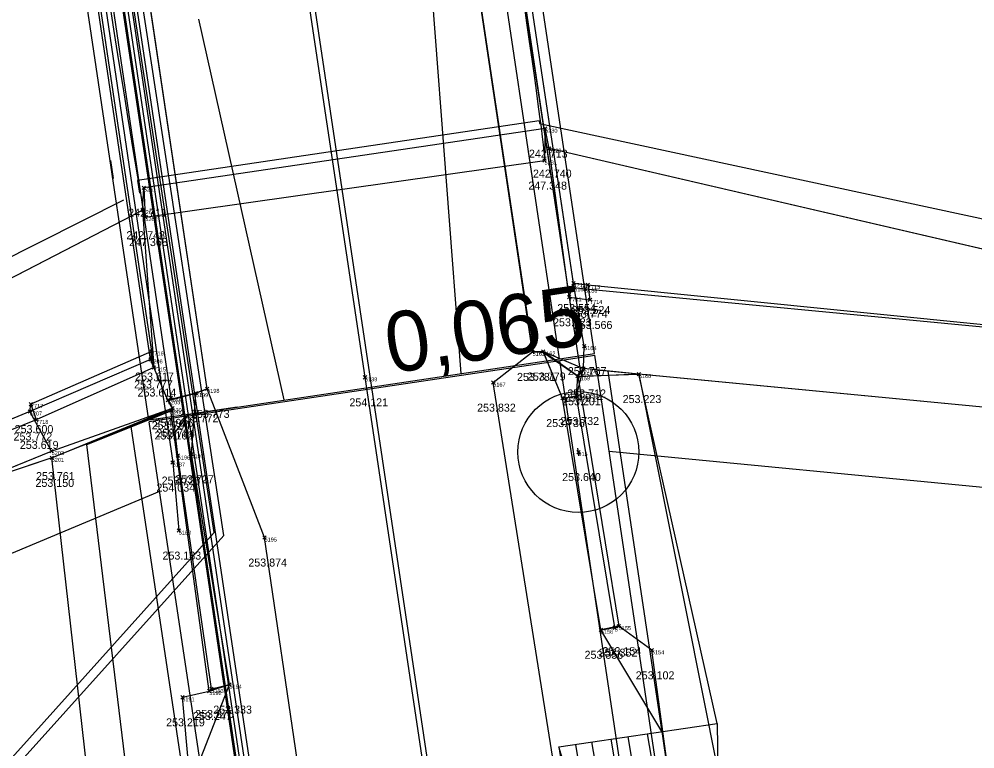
# Model space of a CAD drawing. Extents: x -809973 to -809318, y -1011363 to -1010505.
# Drawn here: x -809864.63 to -809852.68, y -1010880.51 to -1010871.39 of the extents above; entities that cross this region are included whole.
import ezdxf

# ---------------------------------------------------------------- set-up
doc = ezdxf.new("R2010")
doc.units = 0
for name, color, linetype in [('18b - zaměření - čísla bodů', 7, 'Continuous'), ('18c - zaměření - výšky', 7, 'Continuous'), ('Návrh', 7, 'Continuous'), ('SO03 - Železniční svršek', 7, 'Continuous'), ('SO04 - Železniční spodek', 7, 'Continuous'), ('SO05 - Úprava kabelů', 7, 'Continuous'), ('SO_02', 7, 'Continuous'), ('stav_stav', 7, 'Continuous'), ('žel svršek_hrany', 7, 'Continuous')]:
    doc.layers.add(name, color=color, linetype=linetype)

# ---------------------------------------------------------------- blocks, each defined once
blk = doc.blocks.new('POINT_DISPLAY')
for p, q in [((-0.021, -0.021), (0.021, 0.021)), ((-0.021, 0.021), (0.021, -0.021))]:
    blk.add_line(p, q)
blk = doc.blocks.new('rampa')
at = {"layer": 'žel svršek_hrany'}
for p, q in [((-790325.466, -1020009.334), (-790322.95, -1020002.801)), ((-790327.333, -1020008.615), (-790324.882, -1020004.201)), ((-790326.679, -1020008.867), (-790324.882, -1020004.201)), ((-790324.322, -1020004.416), (-790325.466, -1020009.334)), ((-790326.278, -1020009.021), (-790325.731, -1020007.52)), ((-790325.85, -1020009.186), (-790325.303, -1020007.685)), ((-790326.506, -1020008.933), (-790326.284, -1020008.32)), ((-790326.078, -1020009.098), (-790325.856, -1020008.484)), ((-790325.466, -1020009.334), (-790327.333, -1020008.615)), ((-790325.466, -1020009.334), (-790327.333, -1020008.615)), ((-790325.66, -1020009.259), (-790325.438, -1020008.645))]:
    blk.add_line(p, q, dxfattribs=at)

msp = doc.modelspace()

# ---------------------------------------------------------------- linework, layer by layer
at = {"layer": 'Návrh'}
msp.add_line((-809857.286, -1010895.613), (-809869.822, -1010811.804), dxfattribs=at)
at = {"layer": 'SO03 - Železniční svršek'}
for p, q in [((-809858.071, -1010875.559), (-809858.211, -1010875.546)), ((-809858.086, -1010875.549), (-809858.211, -1010875.554)), ((-809857.638, -1010875.859), (-809858.086, -1010875.549)), ((-809857.838, -1010876.123), (-809858.071, -1010875.559)), ((-809856.883, -1010875.823), (-809857.638, -1010875.859)), ((-809855.903, -1010880.191), (-809856.883, -1010875.823)), ((-809862.763, -1010876.152), (-809862.419, -1010876.062)), ((-809862.708, -1010876.25), (-809862.763, -1010876.152)), ((-809857.359, -1010879.02), (-809857.838, -1010876.123)), ((-809863.782, -1010876.706), (-809862.73, -1010876.281)), ((-809862.73, -1010876.281), (-809862.708, -1010876.25)), ((-809863.235, -1010881.193), (-809863.782, -1010876.706)), ((-809856.596, -1010880.293), (-809857.359, -1010879.02)), ((-809862.543, -1010881.091), (-809862, -1010879.706))]:
    msp.add_line(p, q, dxfattribs=at)
for points in [[(-809862, -1010879.706), (-809862.476, -1010876.825), (-809862.419, -1010876.062), (-809862.279, -1010876.008), (-809867.764, -1010839.12), (-809868.277, -1010839.183), (-809869.024, -1010838.237), (-809869.537, -1010834.33)], [(-809863.296, -1010838.436), (-809863.759, -1010838.589), (-809858.21, -1010875.554)]]:
    msp.add_lwpolyline(points, dxfattribs=at)
at = {"layer": 'SO04 - Železniční spodek'}
for points in [[(-809857.269, -1010875.786), (-809854.226, -1010896.132), (-809854.078, -1010897.121)], [(-809863.233, -1010876.477), (-809860.16, -1010897.02)]]:
    msp.add_lwpolyline(points, dxfattribs=at)
at = {"layer": 'SO05 - Úprava kabelů'}
for points in [[(-809832.494, -1011018.409), (-809834.046, -1011017.811), (-809840.102, -1011020.003), (-809840.886, -1011019.699), (-809849.784, -1011002.747), (-809854.105, -1010999.74), (-809859.871, -1010979.608), (-809861.054, -1010971.463), (-809873.181, -1010917.053), (-809875.79, -1010892.925), (-809862.192, -1010877.803), (-809870.3, -1010824.924)], [(-809832.452, -1011018.3), (-809834.045, -1011017.686), (-809840.101, -1011019.878), (-809840.803, -1011019.606), (-809849.694, -1011002.668), (-809854.004, -1010999.668), (-809859.756, -1010979.584), (-809860.94, -1010971.442), (-809873.066, -1010917.034), (-809875.669, -1010892.964), (-809862.069, -1010877.84), (-809862.069, -1010877.84), (-809870.184, -1010824.906)], [(-809832.452, -1011018.3), (-809834.599, -1011012.541), (-809836.558, -1011007.657), (-809839.63, -1011000.177), (-809840.754, -1010995.474), (-809845.885, -1010976.431), (-809847.466, -1010970.457), (-809849.998, -1010958.97), (-809853.746, -1010939.574), (-809862.448, -1010886.367), (-809861.681, -1010881.903), (-809870.184, -1010824.906)], [(-809832.343, -1011018.259), (-809834.49, -1011012.499), (-809836.45, -1011007.613), (-809839.519, -1011000.141), (-809840.641, -1010995.445), (-809845.773, -1010976.401), (-809847.353, -1010970.429), (-809849.884, -1010958.947), (-809853.631, -1010939.554), (-809862.33, -1010886.367), (-809861.563, -1010881.905), (-809870.069, -1010824.889)]]:
    msp.add_lwpolyline(points, dxfattribs=at)
at = {"layer": 'SO_02'}
for p, q in [((-809861.747, -1010881.746), (-809868.926, -1010833.75)), ((-809861.648, -1010881.731), (-809868.827, -1010833.736)), ((-809857.874, -1010875.633), (-809863.458, -1010838.296)), ((-809857.438, -1010875.568), (-809863.023, -1010838.231)), ((-809857.7, -1010874.685), (-809863.148, -1010838.433)), ((-809863.285, -1010838.455), (-809857.753, -1010874.863)), ((-809862.571, -1010876.336), (-809868.156, -1010838.999)), ((-809863.006, -1010876.401), (-809868.591, -1010839.064)), ((-809868.363, -1010839.157), (-809862.976, -1010875.541)), ((-809859.477, -1010870.952), (-809859.109, -1010875.818)), ((-809862.387, -1010871.385), (-809861.319, -1010876.147)), ((-809858.129, -1010872.656), (-809863.148, -1010873.404)), ((-809858.129, -1010872.656), (-809858.124, -1010872.691)), ((-809858.124, -1010872.691), (-809844.481, -1010875.628)), ((-809858.054, -1010872.755), (-809863.071, -1010873.493)), ((-809863.489, -1010873.152), (-809863.455, -1010873.378)), ((-809863.052, -1010873.86), (-809858.062, -1010873.154)), ((-809863.148, -1010873.404), (-809863.125, -1010873.561)), ((-809876.864, -1010880.47), (-809863.32, -1010873.645)), ((-809863.086, -1010873.774), (-809862.946, -1010875.741)), ((-809857.555, -1010874.757), (-809844.518, -1010876.01)), ((-809857.52, -1010874.709), (-809844.518, -1010876.01)), ((-809857.753, -1010874.863), (-809857.494, -1010874.896)), ((-809862.976, -1010875.541), (-809862.989, -1010875.64)), ((-809857.874, -1010875.633), (-809857.438, -1010875.568)), ((-809857.871, -1010875.653), (-809857.435, -1010875.588)), ((-809856.685, -1010880.607), (-809857.435, -1010875.588)), ((-809862.571, -1010876.336), (-809857.874, -1010875.633)), ((-809862.568, -1010876.355), (-809857.871, -1010875.653)), ((-809857.12, -1010880.672), (-809857.871, -1010875.653)), ((-809862.946, -1010875.741), (-809864.417, -1010876.396)), ((-809844.618, -1010877), (-809857.408, -1010875.773)), ((-809844.618, -1010877), (-809856.883, -1010875.823)), ((-809864.497, -1010876.291), (-809864.482, -1010876.198)), ((-809864.223, -1010876.786), (-809864.497, -1010876.291)), ((-809861.904, -1010876.236), (-809862.571, -1010876.336)), ((-809864.417, -1010876.396), (-809876.573, -1010881.314)), ((-809862.571, -1010876.336), (-809863.006, -1010876.401)), ((-809862.568, -1010876.355), (-809863.004, -1010876.421)), ((-809862.253, -1010881.44), (-809863.004, -1010876.421)), ((-809862.677, -1010876.555), (-809862.506, -1010876.324)), ((-809861.818, -1010881.375), (-809862.568, -1010876.355)), ((-809844.714, -1010877.995), (-809857.255, -1010876.792))]:
    msp.add_line(p, q, dxfattribs=at)
for points in [[(-809844.518, -1010876.01), (-809846.267, -1010875.73), (-809858.004, -1010873.004), (-809858.054, -1010872.755), (-809858.062, -1010873.154)], [(-809857.753, -1010874.863), (-809858.004, -1010873.004)], [(-809880.813, -1010883.644), (-809881.049, -1010884.006), (-809881.035, -1010883.822), (-809875.603, -1010880.245), (-809863.086, -1010873.774), (-809863.071, -1010873.493), (-809863.052, -1010873.86)], [(-809857.753, -1010874.863), (-809857.7, -1010874.685), (-809857.52, -1010874.709), (-809857.494, -1010874.896)], [(-809857.691, -1010874.74), (-809857.7, -1010874.685)], [(-809857.691, -1010874.74), (-809857.555, -1010874.757)], [(-809862.946, -1010875.741), (-809862.976, -1010875.541), (-809864.482, -1010876.198), (-809864.417, -1010876.396)], [(-809862.989, -1010875.64), (-809864.497, -1010876.291)], [(-809862.712, -1010876.25), (-809862.734, -1010876.278), (-809864.222, -1010876.871), (-809865.405, -1010877.268), (-809864.223, -1010876.786), (-809862.712, -1010876.25), (-809862.769, -1010876.151)], [(-809864.497, -1010876.291), (-809876.573, -1010881.314), (-809880.813, -1010883.644)], [(-809862.873, -1010877.291), (-809875.888, -1010882.745), (-809880.049, -1010885.032)]]:
    msp.add_lwpolyline(points, dxfattribs=at)
for centre, major_axis, ratio, start_param, end_param in [((-809858.765, -1010868.548), (0.706, -4.61), 0.011125, 6.242864, 9.451152), ((-809863.75, -1010869.267), (0.697, -4.596), 0.009302, 3.125155, 6.319851)]:
    msp.add_ellipse(centre, major_axis=major_axis, ratio=ratio, start_param=start_param, end_param=end_param, dxfattribs=at)
at = {"layer": 'stav_stav'}
for p, q in [((-809857.7, -1010874.685), (-809863.148, -1010838.433)), ((-809863.285, -1010838.455), (-809857.753, -1010874.863)), ((-809863.205, -1010838.533), (-809857.614, -1010875.806)), ((-809857.691, -1010874.74), (-809863.152, -1010838.466)), ((-809858.211, -1010875.546), (-809863.759, -1010838.589)), ((-809863.759, -1010838.589), (-809858.211, -1010875.546)), ((-809868.363, -1010839.157), (-809862.976, -1010875.541)), ((-809868.218, -1010839.075), (-809862.732, -1010876.12)), ((-809862.279, -1010876.008), (-809867.764, -1010839.12)), ((-809862.279, -1010876.008), (-809867.764, -1010839.12)), ((-809862.989, -1010875.64), (-809868.39, -1010839.215)), ((-809868.273, -1010839.19), (-809862.71, -1010876.93)), ((-809860.306, -1010875.864), (-809863.238, -1010856.222)), ((-809858.054, -1010872.755), (-809863.071, -1010873.493)), ((-809858.054, -1010872.755), (-809858.062, -1010873.154)), ((-809858.004, -1010873.004), (-809858.054, -1010872.755)), ((-809857.753, -1010874.863), (-809858.004, -1010873.004)), ((-809846.267, -1010875.73), (-809858.004, -1010873.004)), ((-809863.086, -1010873.774), (-809863.071, -1010873.493)), ((-809863.071, -1010873.493), (-809863.052, -1010873.86)), ((-809875.603, -1010880.245), (-809863.086, -1010873.774)), ((-809863.086, -1010873.774), (-809862.946, -1010875.741)), ((-809857.753, -1010874.863), (-809857.7, -1010874.685)), ((-809857.691, -1010874.74), (-809857.7, -1010874.685)), ((-809857.7, -1010874.685), (-809857.52, -1010874.709)), ((-809857.691, -1010874.74), (-809857.555, -1010874.757)), ((-809857.568, -1010875.474), (-809857.691, -1010874.74)), ((-809857.555, -1010874.757), (-809844.518, -1010876.01)), ((-809857.52, -1010874.709), (-809844.518, -1010876.01)), ((-809857.52, -1010874.709), (-809857.494, -1010874.896)), ((-809857.753, -1010874.863), (-809857.494, -1010874.896)), ((-809857.575, -1010875.753), (-809857.568, -1010875.474)), ((-809862.976, -1010875.541), (-809864.482, -1010876.198)), ((-809862.976, -1010875.541), (-809862.989, -1010875.64)), ((-809862.946, -1010875.741), (-809862.976, -1010875.541)), ((-809858.703, -1010875.93), (-809858.211, -1010875.546)), ((-809858.079, -1010875.541), (-809858.211, -1010875.546)), ((-809858.211, -1010875.546), (-809858.079, -1010875.541)), ((-809857.838, -1010876.123), (-809858.079, -1010875.541)), ((-809858.079, -1010875.541), (-809857.575, -1010875.753)), ((-809857.648, -1010875.851), (-809858.079, -1010875.541)), ((-809857.838, -1010876.123), (-809858.079, -1010875.541)), ((-809858.079, -1010875.541), (-809857.648, -1010875.851)), ((-809858.079, -1010875.541), (-809857.575, -1010875.753)), ((-809862.989, -1010875.64), (-809864.497, -1010876.291)), ((-809862.769, -1010876.151), (-809862.989, -1010875.64)), ((-809862.946, -1010875.741), (-809864.417, -1010876.396)), ((-809857.662, -1010876.097), (-809857.575, -1010875.753)), ((-809857.648, -1010875.851), (-809857.575, -1010875.753)), ((-809857.575, -1010875.753), (-809857.648, -1010875.851)), ((-809857.648, -1010875.851), (-809856.883, -1010875.823)), ((-809856.883, -1010875.823), (-809857.575, -1010875.753)), ((-809844.618, -1010877), (-809856.883, -1010875.823)), ((-809856.883, -1010875.823), (-809855.422, -1010883.15)), ((-809844.618, -1010877), (-809856.883, -1010875.823)), ((-809858.786, -1010885.982), (-809860.306, -1010875.864)), ((-809857.441, -1010883.897), (-809858.703, -1010875.93)), ((-809857.662, -1010876.097), (-809857.648, -1010875.851)), ((-809857.648, -1010875.851), (-809857.134, -1010878.975)), ((-809862.419, -1010876.062), (-809862.769, -1010876.151)), ((-809862.419, -1010876.062), (-809862.769, -1010876.151)), ((-809862.476, -1010876.825), (-809862.419, -1010876.062)), ((-809862.476, -1010876.825), (-809862.419, -1010876.062)), ((-809862.279, -1010876.008), (-809862.419, -1010876.062)), ((-809862.419, -1010876.062), (-809862.279, -1010876.008)), ((-809861.561, -1010877.867), (-809862.279, -1010876.008)), ((-809864.497, -1010876.291), (-809864.482, -1010876.198)), ((-809864.482, -1010876.198), (-809864.417, -1010876.396)), ((-809862.712, -1010876.25), (-809862.769, -1010876.151)), ((-809862.769, -1010876.151), (-809862.712, -1010876.25)), ((-809857.838, -1010876.123), (-809857.662, -1010876.097)), ((-809857.359, -1010879.02), (-809857.838, -1010876.123)), ((-809857.359, -1010879.02), (-809857.838, -1010876.123)), ((-809857.183, -1010878.994), (-809857.662, -1010876.097)), ((-809864.497, -1010876.291), (-809876.573, -1010881.314)), ((-809864.223, -1010876.786), (-809864.497, -1010876.291)), ((-809864.223, -1010876.786), (-809862.712, -1010876.25)), ((-809864.222, -1010876.871), (-809862.712, -1010876.25)), ((-809862.734, -1010876.278), (-809864.222, -1010876.871)), ((-809862.734, -1010876.278), (-809864.222, -1010876.871)), ((-809862.712, -1010876.25), (-809862.734, -1010876.278)), ((-809862.712, -1010876.25), (-809862.734, -1010876.278)), ((-809862.252, -1010879.786), (-809862.734, -1010876.278)), ((-809862.645, -1010876.842), (-809862.712, -1010876.25)), ((-809864.417, -1010876.396), (-809876.573, -1010881.314)), ((-809865.405, -1010877.268), (-809864.223, -1010876.786)), ((-809857.632, -1010876.847), (-809857.646, -1010876.749)), ((-809864.222, -1010876.871), (-809865.405, -1010877.268)), ((-809864.222, -1010876.871), (-809865.405, -1010877.268)), ((-809863.59, -1010882.451), (-809864.222, -1010876.871)), ((-809862.226, -1010879.76), (-809862.645, -1010876.842)), ((-809862, -1010879.706), (-809862.476, -1010876.825)), ((-809862, -1010879.706), (-809862.476, -1010876.825)), ((-809862.71, -1010876.93), (-809862.634, -1010877.78)), ((-809857.871, -1010903.005), (-809861.561, -1010877.867)), ((-809857.134, -1010878.975), (-809857.359, -1010879.02)), ((-809857.134, -1010878.975), (-809857.359, -1010879.02)), ((-809857.359, -1010879.02), (-809857.183, -1010878.994)), ((-809857.183, -1010878.994), (-809857.134, -1010878.975)), ((-809856.72, -1010879.277), (-809857.134, -1010878.975)), ((-809856.171, -1010883.326), (-809856.72, -1010879.277)), ((-809862.589, -1010879.865), (-809862.252, -1010879.786)), ((-809862, -1010879.706), (-809862.252, -1010879.786)), ((-809862.252, -1010879.786), (-809862, -1010879.706)), ((-809862.252, -1010879.786), (-809862.226, -1010879.76)), ((-809862.226, -1010879.76), (-809862, -1010879.706)), ((-809862.455, -1010881.274), (-809862.589, -1010879.865))]:
    msp.add_line(p, q, dxfattribs=at)
msp.add_circle((-809857.639, -1010876.798), 0.756, dxfattribs=at)
for centre, major_axis, ratio, start_param, end_param in [((-809858.765, -1010868.548), (0.706, -4.61), 0.011125, 6.242864, 9.451152), ((-809863.75, -1010869.267), (0.697, -4.596), 0.009302, 3.125155, 6.319851)]:
    msp.add_ellipse(centre, major_axis=major_axis, ratio=ratio, start_param=start_param, end_param=end_param, dxfattribs=at)

# ---------------------------------------------------------------- block references
at = {"layer": '18b - zaměření - čísla bodů'}
for p in [(-809858.054, -1010872.755), (-809858.004, -1010873.004), (-809858.062, -1010873.154), (-809863.071, -1010873.493), (-809863.086, -1010873.774), (-809863.052, -1010873.86), (-809857.7, -1010874.685), (-809857.691, -1010874.74), (-809857.555, -1010874.757), (-809857.52, -1010874.709), (-809857.753, -1010874.863), (-809857.494, -1010874.896), (-809857.568, -1010875.474), (-809862.976, -1010875.541), (-809858.211, -1010875.546), (-809858.079, -1010875.541), (-809862.989, -1010875.64), (-809862.946, -1010875.741), (-809860.306, -1010875.864), (-809857.648, -1010875.851), (-809857.614, -1010875.806), (-809857.575, -1010875.753), (-809856.883, -1010875.823), (-809858.703, -1010875.93), (-809862.419, -1010876.062), (-809862.279, -1010876.008), (-809857.662, -1010876.097), (-809864.482, -1010876.198), (-809862.769, -1010876.151), (-809862.732, -1010876.12), (-809857.838, -1010876.123), (-809864.497, -1010876.291), (-809862.734, -1010876.278), (-809862.712, -1010876.25), (-809864.417, -1010876.396), (-809864.223, -1010876.786), (-809857.639, -1010876.798), (-809864.222, -1010876.871), (-809862.71, -1010876.93), (-809862.645, -1010876.842), (-809862.476, -1010876.825), (-809862.634, -1010877.78), (-809861.561, -1010877.867), (-809857.359, -1010879.02), (-809857.183, -1010878.994), (-809857.134, -1010878.975), (-809856.72, -1010879.277), (-809862.252, -1010879.786), (-809862.226, -1010879.76), (-809862, -1010879.706), (-809862.589, -1010879.865)]:
    msp.add_blockref('POINT_DISPLAY', p, dxfattribs=at)
at = {"layer": 'žel svršek_hrany', "rotation": -150.50675896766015}
msp.add_blockref('rampa', (-995596.16, -2287804.395), dxfattribs=at)

# ---------------------------------------------------------------- texts
at = {"layer": '18b - zaměření - čísla bodů'}
for s, p in [('5230', (-809858.054, -1010872.805)), ('5229', (-809858.004, -1010873.054)), ('5231', (-809858.062, -1010873.204)), ('5261', (-809863.071, -1010873.543)), ('5260', (-809863.086, -1010873.824)), ('5262', (-809863.052, -1010873.91)), ('7712', (-809857.7, -1010874.735)), ('5165', (-809857.691, -1010874.79)), ('5166', (-809857.555, -1010874.807)), ('7713', (-809857.52, -1010874.759)), ('7711', (-809857.753, -1010874.913)), ('7714', (-809857.494, -1010874.946)), ('5164', (-809857.568, -1010875.524)), ('7716', (-809862.976, -1010875.591)), ('5163', (-809858.211, -1010875.596)), ('5162', (-809858.079, -1010875.591)), ('5206', (-809862.989, -1010875.69)), ('7715', (-809862.946, -1010875.791)), ('5150', (-809857.614, -1010875.856)), ('5161', (-809857.575, -1010875.803)), ('5160', (-809856.883, -1010875.873)), ('5139', (-809860.306, -1010875.914)), ('5167', (-809858.703, -1010875.98)), ('5159', (-809857.648, -1010875.901)), ('5199', (-809862.419, -1010876.112)), ('5198', (-809862.279, -1010876.058)), ('7717', (-809864.482, -1010876.248)), ('5205', (-809862.769, -1010876.201)), ('5208', (-809862.732, -1010876.17)), ('5157', (-809857.838, -1010876.173)), ('5158', (-809857.662, -1010876.147)), ('5207', (-809864.497, -1010876.341)), ('5200', (-809862.734, -1010876.328)), ('5204', (-809862.712, -1010876.3)), ('7718', (-809864.417, -1010876.446)), ('5203', (-809864.223, -1010876.836)), ('915', (-809857.639, -1010876.848)), ('5201', (-809864.222, -1010876.921)), ('5196', (-809862.645, -1010876.892)), ('5197', (-809862.476, -1010876.875)), ('5187', (-809862.71, -1010876.98)), ('5188', (-809862.634, -1010877.83)), ('5195', (-809861.561, -1010877.917)), ('5156', (-809857.359, -1010879.07)), ('6', (-809857.183, -1010879.044)), ('5155', (-809857.134, -1010879.025)), ('5154', (-809856.72, -1010879.327)), ('5192', (-809862.252, -1010879.836)), ('5193', (-809862.226, -1010879.81)), ('5194', (-809862, -1010879.756)), ('5191', (-809862.589, -1010879.915))]:
    msp.add_text(s, height=0.05, dxfattribs=at).set_placement(p)
at = {"layer": '18c - zaměření - výšky'}
for s, p in [('242.713', (-809858.257, -1010873.118)), ('242.740', (-809858.207, -1010873.367)), ('247.348', (-809858.265, -1010873.517)), ('242.711', (-809863.266, -1010873.856)), ('242.748', (-809863.289, -1010874.137)), ('247.368', (-809863.255, -1010874.223)), ('253.554', (-809857.903, -1010875.048)), ('253.772', (-809857.893, -1010875.103)), ('253.524', (-809857.723, -1010875.072)), ('253.523', (-809857.956, -1010875.226)), ('253.774', (-809857.758, -1010875.12)), ('253.566', (-809857.697, -1010875.259)), ('253.617', (-809863.179, -1010875.904)), ('253.781', (-809858.406, -1010875.909)), ('253.779', (-809858.282, -1010875.904)), ('253.767', (-809857.771, -1010875.837)), ('253.777', (-809863.192, -1010876.003)), ('253.614', (-809863.149, -1010876.104)), ('254.914', (-809857.817, -1010876.169)), ('253.712', (-809857.777, -1010876.116)), ('253.223', (-809857.086, -1010876.186)), ('254.121', (-809860.501, -1010876.227)), ('253.832', (-809858.905, -1010876.293)), ('253.201', (-809857.843, -1010876.214)), ('253.772', (-809862.621, -1010876.425)), ('253.773', (-809862.482, -1010876.371)), ('253.794', (-809862.972, -1010876.514)), ('254.916', (-809862.935, -1010876.483)), ('253.736', (-809858.041, -1010876.486)), ('253.732', (-809857.864, -1010876.46)), ('253.772', (-809864.699, -1010876.654)), ('253.600', (-809864.685, -1010876.561)), ('253.162', (-809862.936, -1010876.641)), ('253.784', (-809862.915, -1010876.613)), ('253.619', (-809864.62, -1010876.759)), ('253.150', (-809864.425, -1010877.234)), ('253.761', (-809864.418, -1010877.149)), ('253.726', (-809862.848, -1010877.205)), ('253.727', (-809862.679, -1010877.188)), ('253.640', (-809857.842, -1010877.161)), ('254.034', (-809862.913, -1010877.293)), ('253.183', (-809862.837, -1010878.143)), ('253.874', (-809861.764, -1010878.23)), ('253.356', (-809857.562, -1010879.383)), ('253.352', (-809857.385, -1010879.357)), ('253.154', (-809857.337, -1010879.338)), ('253.102', (-809856.922, -1010879.64)), ('253.376', (-809862.429, -1010880.123)), ('253.333', (-809862.203, -1010880.069)), ('253.219', (-809862.792, -1010880.228)), ('253.247', (-809862.455, -1010880.149))]:
    msp.add_text(s, height=0.1, dxfattribs=at).set_placement(p)
at = {"layer": 'SO03 - Železniční svršek'}
msp.add_text('0,065', height=0.75, rotation=8.5071, dxfattribs=at).set_placement((-809859.995, -1010875.817))

doc.saveas('drawing.dxf')
